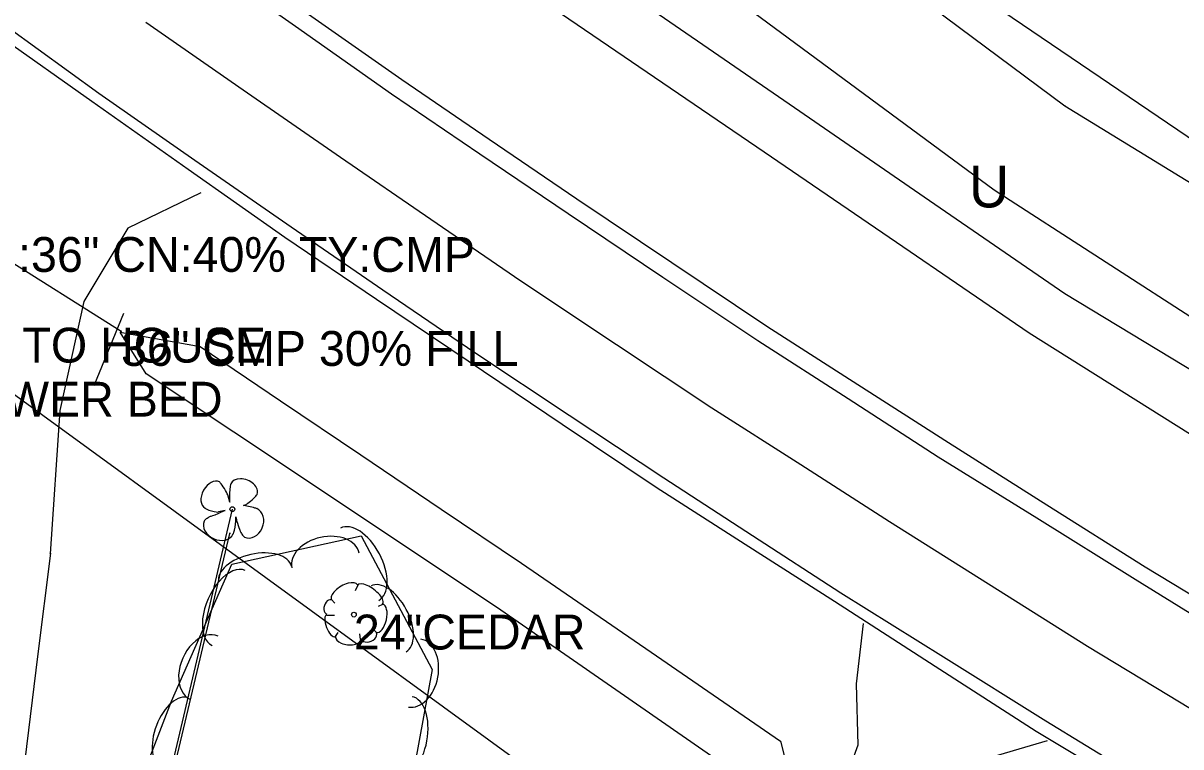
# Model space of a CAD drawing. Extents: x 1441650 to 1491889, y 345904 to 358319.
# Drawn here: x 1445119.8 to 1445285.8, y 354818.8 to 354922.6 of the extents above; entities that cross this region are included whole.
import ezdxf

# ---------------------------------------------------------------- set-up
doc = ezdxf.new("R2010")
doc.units = 0
for name, color, linetype in [('Default', 7, 'Continuous'), ('S_CROSS_DRAIN', 7, 'Continuous'), ('S_CROSS_DRAIN_ANNOT', 7, 'Continuous'), ('S_DITCHLINE', 7, 'Continuous'), ('S_DRG_PT_SYM', 7, 'Continuous'), ('S_EDGE_PAVEMENT', 7, 'Continuous'), ('S_FENCE', 7, 'Continuous'), ('S_GAS_UTILITIES', 7, 'Continuous'), ('S_GRAVEL_ROAD', 7, 'Continuous'), ('S_HEADWALL', 7, 'Continuous'), ('S_MSC_PT_SYM', 7, 'Continuous'), ('S_PAVEMENT_CROWN', 7, 'Continuous'), ('S_SHOULDER', 7, 'Continuous'), ('S_SURVEY_TEXT_ANNOT', 7, 'Continuous'), ('S_TREE', 7, 'Continuous'), ('S_TREE_ANNOT', 7, 'Continuous'), ('S_UNDERGROUND_CABLE', 7, 'Continuous'), ('S_UTL_PT_SYM', 7, 'Continuous'), ('S_WATER_UTILITIES', 7, 'Continuous')]:
    doc.layers.add(name, color=color, linetype=linetype)

msp = doc.modelspace()

# ---------------------------------------------------------------- linework, layer by layer
at = {"layer": 'S_CROSS_DRAIN'}
msp.add_line((1445112.33, 354891.94), (1445133.79, 354878.46), dxfattribs=at)
at = {"layer": 'S_DITCHLINE'}
for points in [[(1444997.06, 355086.08), (1444994.71, 355076.39), (1444997, 355068.99), (1445010.45, 355057.09), (1445023.9, 355045.18), (1445033.89, 355037.54), (1445043.88, 355029.9), (1445053.87, 355022.26), (1445063.86, 355014.62), (1445073.85, 355006.99), (1445083.84, 354999.35), (1445093.83, 354991.71), (1445103.82, 354984.07), (1445124.85, 354970.58), (1445145.89, 354957.09), (1445166.93, 354943.6), (1445187.97, 354930.11), (1445206.99, 354917.13), (1445226.02, 354904.16), (1445245.04, 354891.19), (1445264.06, 354878.21), (1445279.36, 354868.59), (1445294.65, 354858.97)], [(1444997.06, 355086.08), (1445000.78, 355084.76), (1445005.58, 355079.74), (1445019.02, 355068.19), (1445032.47, 355056.64), (1445052.49, 355041.67), (1445072.51, 355026.7), (1445092.53, 355011.72), (1445112.55, 354996.75), (1445132.31, 354981.87), (1445152.07, 354966.98), (1445171.84, 354952.1), (1445191.6, 354937.22), (1445210.99, 354923.87), (1445230.38, 354910.53), (1445249.78, 354897.18), (1445269.17, 354883.84), (1445284.43, 354874.6), (1445299.68, 354865.37), (1445314.94, 354856.13), (1445330.2, 354846.89), (1445331.86, 354840.04)]]:
    msp.add_lwpolyline(points, dxfattribs=at)
msp.add_lwpolyline([(1445133.69, 354878.31), (1445145.12, 354876.22), (1445156.65, 354868.46), (1445168.18, 354860.69), (1445179.71, 354852.93), (1445191.24, 354845.17), (1445209.83, 354832.39), (1445228.41, 354819.61), (1445230.13, 354812.91), (1445223.16, 354814.25), (1445205.4, 354826.54), (1445187.64, 354838.83), (1445175.09, 354847.2), (1445162.53, 354855.58), (1445149.98, 354863.95), (1445137.42, 354872.33)], close=True, dxfattribs=at)
at = {"layer": 'S_DRG_PT_SYM'}
msp.add_lwpolyline([(1445133.79, 354878.46), (1445133.79, 354878.51), (1445133.79, 354878.46), (1445133.74, 354878.46), (1445133.79, 354878.46), (1445133.79, 354878.41), (1445133.79, 354878.46), (1445133.84, 354878.46)], dxfattribs=at)
at = {"layer": 'S_EDGE_PAVEMENT'}
for points in [[(1445104.48, 354931.44), (1445117.54, 354922.02), (1445130.6, 354912.6), (1445144.39, 354902.99), (1445158.18, 354893.39), (1445171.35, 354884.38), (1445184.53, 354875.37), (1445198.09, 354866.37), (1445211.64, 354857.38), (1445224.35, 354849.14), (1445237.06, 354840.89), (1445251.76, 354831.71), (1445266.45, 354822.53), (1445278.03, 354815.47), (1445289.61, 354808.41)], [(1445144.99, 354931.9), (1445158.8, 354922.18), (1445172.6, 354912.47), (1445185.25, 354903.89), (1445197.91, 354895.31), (1445211.52, 354886.2), (1445225.13, 354877.09), (1445238.08, 354868.76), (1445251.02, 354860.43), (1445265.14, 354851.65), (1445279.26, 354842.86), (1445290.79, 354835.73)]]:
    msp.add_lwpolyline(points, dxfattribs=at)
at = {"layer": 'S_FENCE'}
msp.add_line((1445139.86, 354809.22), (1445149.39, 354849.44), dxfattribs=at)
at = {"layer": 'S_GAS_UTILITIES'}
msp.add_line((1444980.37, 355114.9), (1445467.8, 354783.19), dxfattribs=at)
at = {"layer": 'S_GRAVEL_ROAD'}
for points in [[(1445145.25, 354898.26), (1445134.77, 354893.19), (1445128.47, 354882.68), (1445125.02, 354867.07), (1445123.61, 354846.52), (1445123.67, 354846.62), (1445121.82, 354831.77), (1445119.97, 354816.92)], [(1445240.23, 354836.51), (1445239.23, 354827.85), (1445239.49, 354819.07), (1445236.48, 354810.72), (1445227.52, 354799.71), (1445218.56, 354788.71), (1445212.4, 354777.92), (1445204.27, 354766.46), (1445222.43, 354758.3), (1445229.22, 354773.13), (1445237.54, 354790.26), (1445244.54, 354804.35), (1445250.33, 354812.56), (1445256.45, 354816.73), (1445266.68, 354819.75)]]:
    msp.add_lwpolyline(points, dxfattribs=at)
at = {"layer": 'S_HEADWALL'}
msp.add_lwpolyline([(1445129.94, 354870.63), (1445134.21, 354881.01)], dxfattribs=at)
at = {"layer": 'S_MSC_PT_SYM'}
msp.add_lwpolyline([(1445149.39, 354849.44), (1445149.39, 354849.49), (1445149.39, 354849.44), (1445149.34, 354849.44), (1445149.39, 354849.44), (1445149.39, 354849.39), (1445149.39, 354849.44), (1445149.44, 354849.44)], dxfattribs=at)
at = {"layer": 'S_PAVEMENT_CROWN'}
msp.add_lwpolyline([(1445137.33, 354922.74), (1445151.31, 354913.07), (1445165.29, 354903.39), (1445178.21, 354894.52), (1445191.14, 354885.65), (1445204.85, 354876.55), (1445218.56, 354867.45), (1445231.3, 354859.31), (1445244.03, 354851.16), (1445258.22, 354842.21), (1445272.41, 354833.26), (1445284.06, 354826.21), (1445295.71, 354819.16)], dxfattribs=at)
at = {"layer": 'S_SHOULDER'}
for points in [[(1445103.05, 354930.2), (1445116.32, 354920.82), (1445129.59, 354911.44), (1445143.44, 354901.68), (1445157.3, 354891.92), (1445170.43, 354883.05), (1445183.57, 354874.18), (1445197.06, 354865.12), (1445210.55, 354856.07), (1445223.33, 354847.89), (1445236.12, 354839.71), (1445250.59, 354830.39), (1445265.05, 354821.07), (1445276.89, 354813.98), (1445288.72, 354806.89)], [(1445160.22, 354924.22), (1445174.07, 354914.55), (1445186.62, 354905.98), (1445199.17, 354897.41), (1445212.8, 354888.28), (1445226.43, 354879.15), (1445239.46, 354870.8), (1445252.49, 354862.45), (1445266.6, 354853.54), (1445280.7, 354844.63), (1445292.3, 354837.59)]]:
    msp.add_lwpolyline(points, dxfattribs=at)
at = {"layer": 'S_TREE'}
for p, q in [((1445149.39, 354853.89), (1445149.15, 354854.79)), ((1445139.51, 354809.19), (1445149.76, 354852.91)), ((1445148.74, 354852.73), (1445147.77, 354852.51)), ((1445151.34, 354853.43), (1445151.72, 354853.6)), ((1445150.28, 354851.8), (1445150.36, 354851.36)), ((1445167.75, 354842.02), (1445167.36, 354841.17)), ((1445163.95, 354840.01), (1445164.46, 354839.43)), ((1445171.32, 354839.23), (1445170.66, 354838.96)), ((1445163.29, 354837.68), (1445164.42, 354837.68)), ((1445164.46, 354834.51), (1445164.92, 354835.2)), ((1445168.14, 354834.23), (1445168.06, 354835.01)), ((1445170.54, 354835.13), (1445170.08, 354835.55))]:
    msp.add_line(p, q, dxfattribs=at)
msp.add_lwpolyline([(1445062.66, 354737.7), (1445036.25, 354743.75), (1445018.34, 354758.77), (1445002, 354780.57), (1445008.72, 354803.48), (1445034.19, 354809.69), (1445078.19, 354795.67), (1445109.88, 354793.21), (1445132.32, 354802.76), (1445141.03, 354825.37), (1445149.69, 354845.03), (1445168.23, 354849.09), (1445178.41, 354829.92), (1445171.6, 354792.55), (1445175.47, 354753.75), (1445190.97, 354727.66), (1445216.54, 354694.19), (1445235.93, 354674.69), (1445255.34, 354667.34), (1445272.22, 354672.85), (1445290.88, 354695.22)], dxfattribs=at)
for centre in [(1445149.76, 354852.91), (1445167.19, 354837.78)]:
    msp.add_circle(centre, 0.341, dxfattribs=at)
for centre, major_axis, ratio, start_param, end_param in [((1445146.87, 354854.93), (-1.03, -1.88), 0.662338, 3.141593, 6.283185), ((1445148.53, 354855.8), (0.62, -1.01), 0.083512, 0, 3.141593), ((1445149.46, 354855.22), (-0.07, -1.33), 0.068203, 3.141593, 6.283185), ((1445151.42, 354855.8), (1.89, -0.74), 0.673998, 0, 3.141593), ((1445152.52, 354854.33), (-0.798, -0.73), 0.092159, 0, 3.141593), ((1445146.8, 354852.78), (0.964, -0.267), 0.113563, 3.141593, 6.283185), ((1445147.7, 354852.29), (1.04, 0.44), 0.002756, 3.141593, 6.283185), ((1445152.3, 354853.2), (0.96, -0.23), 0.056001, 0, 3.141593), ((1445152.38, 354850.93), (0.88, 2.05), 0.81717, 3.141593, 6.283185), ((1445147.78, 354850.25), (2.07, -0.93), 0.760068, 3.141593, 6.283185), ((1445146.19, 354851.52), (0.477, 0.328), 0.136309, 0, 3.141593), ((1445150.04, 354850.63), (0.19, 1.31), 0.114148, 3.141593, 5.822668), ((1445150.61, 354850.59), (0.254, -0.771), 0.051603, 3.141593, 6.283185), ((1445168, 354845), (-2.75, 5.18), 0.550059, 3.141593, 6.283185), ((1445151.18, 354849.35), (-0.321, 0.467), 0.094289, 0, 3.141593), ((1445163.13, 354845.54), (-4.84, -1.06), 0.685178, 3.141593, 6.283185), ((1445153.01, 354843.59), (-5.22, -1.14), 0.540594, 3.141593, 6.283185), ((1445149.24, 354838.74), (-2.37, -5.37), 0.549931, 3.141553, 6.283146), ((1445165.86, 354840.98), (1.86, 1.08), 0.471018, 0, 3.141593), ((1445169.51, 354840.66), (-1.81, 1.36), 0.405113, 3.141593, 6.283186), ((1445172.16, 354837.17), (-2.51, 4.72), 0.540679, 3.141593, 6.283185), ((1445163.62, 354838.87), (0.31, 1.03), 0.646762, 0, 3.141593), ((1445163.93, 354836.21), (-0.61, 1.6), 0.420543, 6.283185, 9.424777), ((1445170.87, 354837.25), (0.46, 2.04), 0.482994, 3.141593, 6.283185), ((1445145.74, 354830.16), (-2, -4.53), 0.685125, 3.141528, 6.283121), ((1445166.39, 354834.43), (-1.83, 0.19), 0.529943, 0, 3.141593), ((1445169.35, 354834.73), (1.09, 0.46), 0.711534, 3.141592, 6.283185), ((1445175.9, 354829.4), (0.89, 4.87), 0.685159, 3.141593, 6.283185), ((1445141.57, 354820.86), (-1.92, -4.99), 0.540597, 3.141377, 6.282969), ((1445174.49, 354820.24), (1.05, 5.77), 0.549958, 3.141593, 6.283185)]:
    msp.add_ellipse(centre, major_axis=major_axis, ratio=ratio, start_param=start_param, end_param=end_param, dxfattribs=at)
at = {"layer": 'S_UNDERGROUND_CABLE'}
for p, q in [((1445063.46, 355043.03), (1445259.04, 354898.73)), ((1445259.04, 354898.73), (1445326.11, 354855.37))]:
    msp.add_line(p, q, dxfattribs=at)
at = {"layer": 'S_UTL_PT_SYM'}
msp.add_lwpolyline([(1445269.15, 354910.76), (1445269.15, 354910.81), (1445269.15, 354910.76), (1445269.1, 354910.76), (1445269.15, 354910.76), (1445269.15, 354910.71), (1445269.15, 354910.76), (1445269.2, 354910.76)], dxfattribs=at)
at = {"layer": 'S_WATER_UTILITIES'}
for p, q in [((1445007.53, 355105.91), (1445269.15, 354910.76)), ((1444933.86, 355003.67), (1445212.56, 354800.91)), ((1445269.15, 354910.76), (1445447.71, 354801.29))]:
    msp.add_line(p, q, dxfattribs=at)

# ---------------------------------------------------------------- texts
at = {"layer": 'Default'}
msp.add_text('U', height=6, rotation=360, dxfattribs=at).set_placement((1445255.41, 354896.19))
at = {"layer": 'S_CROSS_DRAIN_ANNOT'}
for s, p in [('DI:36" CN:40% TY:CMP', (1445112.33, 354886.94)), ('36" CMP 30% FILL', (1445133.79, 354873.46))]:
    msp.add_text(s, height=5, dxfattribs=at).set_placement(p)
at = {"layer": 'S_SURVEY_TEXT_ANNOT'}
for s, p in [('TO HOUSE', (1445119.65, 354873.93)), ('FLOWER BED', (1445104.15, 354866.18))]:
    msp.add_text(s, height=5, dxfattribs=at).set_placement(p)
at = {"layer": 'S_TREE_ANNOT'}
msp.add_text('24"CEDAR', height=5, dxfattribs=at).set_placement((1445167.19, 354832.78))

doc.saveas('drawing.dxf')
